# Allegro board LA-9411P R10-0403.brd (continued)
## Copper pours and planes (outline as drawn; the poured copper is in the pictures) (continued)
N78964443 on TOP (solid shape): 69.99,176.45 69.99,174.03 69.73,173.77 67.64,173.77 67.31,174.1 67.31,174.99 67.31,175 67.31,176.42 67.3,176.43 67.3,176.79 67.37,176.86 69.58,176.86
N78967013 on TOP (solid shape): 68.88,172.71 68.88,171.77 68.93,171.72 70.76,171.72 70.84,171.79 71.24,171.79 71.32,171.72 71.32,171.16 71.17,171.01 71.14,171.01 70.91,170.78 68.09,170.78 67.81,171.06 67.81,172.58 68.05,172.82 68.77,172.82
N79030745 on TOP (solid shape): 49.73,173.95 49.73,172.21 49.07,171.55 46.13,171.55 46.02,171.67 46.02,173.28 46.13,173.39 47.51,173.39 48.27,174.15 49.53,174.15
N79031357 on TOP (solid shape): 59.45,179.76 59.9,179.76 60.09,179.58 60.09,178.11 60.02,178.04 59.48,178.04 59.42,178.11 59.42,178.69 59.3,178.8 58.77,178.8 58.19,179.39 57.63,179.39 57.44,179.2 57.44,178.36 57.33,178.24 56.02,178.24 55.88,178.38 55.88,179.95 56.01,180.08 59.13,180.08
N79031404 on TOP (solid shape): 54.86,177.95 54.86,177.51 54.8,177.44 54.35,177.44 53.75,176.85 53.75,176.19 53.59,176.02 52.81,176.02 52.74,176.1 52.74,176.69 52.79,176.75 53.32,176.75 53.77,177.19 53.77,177.76 54.01,178 54.81,178
N79031406 on TOP (solid shape): 53.55,178.55 53.55,177.16 53.4,177.01 52.75,177.01 52.19,176.45 50.53,176.45 50.29,176.69 50.29,177.67 50.53,177.91 52.31,177.91 52.57,178.18 52.57,178.73 52.68,178.83 53.27,178.83
N79031414 on TOP (solid shape): 49.88,180.16 49.88,177.93 49.13,177.18 49.13,176.35 47.99,175.21 47.99,174.07 47.56,173.63 46.5,173.63 46.43,173.71 46.43,176.02 47.75,177.34 47.75,180.44 47.81,180.5 49.54,180.5
N85751870 on TOP (solid shape): 239.63,13.98 239.63,13.22 239.5,13.09 237.22,13.09 237.09,13.22 237.09,13.98 237.22,14.11 239.5,14.11
N91583245 on TOP (solid shape): 346.01,167.88 348.78,167.88 348.8,167.86 348.8,166.38 348.78,166.36 348.03,166.36 347.87,166.51 347.87,166.98 347.61,167.25 346.25,167.25 345.04,168.45 344.38,168.45 344.33,168.5 344.33,168.68 344.39,168.74 345.14,168.74
N111681891 on TOP (solid shape): 189.28,107.51 189.28,105.27 188.9,104.89 187.37,104.89 187.18,105.08 187.18,107.2 187.27,107.29 188.15,107.29 188.4,107.54 189.24,107.54
N116650187 on TOP (solid shape): 114.93,190.13 114.93,188.71 114.78,188.56 113.7,188.56 113.55,188.71 113.55,190.18 113.71,190.35 114.71,190.35
N123100505 on TOP (solid shape): 153.33,6.07 153.33,5.64 153.18,5.49 152.47,5.49 152.16,5.81 152.16,6.36 152.18,6.38 153.02,6.38
N123208235 on TOP (solid shape): 111.55,185.65 111.55,185.11 111.2,184.76 109.08,184.76 108.35,184.04 106.89,184.04 106.65,184.28 106.65,185.71 106.88,185.94 111.26,185.94
N127056523 on TOP (solid shape): 324.65,203.97 324.65,202.76 324.54,202.65 324.54,201.81 324.45,201.72 324.32,201.72 324.24,201.8 324.24,203.14 323.94,203.44 323.94,204.02 323.97,204.05 324.57,204.05
N127056527 on TOP (solid shape): 325.57,203.93 325.57,203.5 325.33,203.26 325.33,201.8 325.27,201.73 325.11,201.73 325.07,201.77 325.07,203.16 324.85,203.39 324.85,203.95 324.92,204.02 325.47,204.02
N127916603 on BOTTOM (solid shape): 343.39,174.13 343.39,172.48 343.26,172.35 342.76,172.35 342.63,172.48 342.63,174.13 342.76,174.26 343.26,174.26
N127916606 on BOTTOM (solid shape): 342.37,174.13 342.37,172.48 342.25,172.35 341.74,172.35 341.61,172.48 341.61,174.13 341.74,174.26 342.25,174.26
N127916609 on BOTTOM (solid shape): 340.47,174.13 340.47,172.48 340.34,172.35 339.83,172.35 339.71,172.48 339.71,174.13 339.83,174.26 340.34,174.26
N127916612 on BOTTOM (solid shape): 341.36,174.13 341.36,172.48 341.23,172.35 340.72,172.35 340.6,172.48 340.6,174.13 340.72,174.26 341.23,174.26

Small or netless copper shapes (teardrops, artwork), in the pictures only: 44 on TOP, 391 on BOTTOM, 1 on GND1, 1 on GND3

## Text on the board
Ref Des/Silkscreen Bottom: LABEL | DDR3L | DIMM A | DIMM B | P
User.Comments: LA-9411P | Lily_tang | 2013-04-03 | 2014-04-03 | VALA0 | 1.0(A00)
Ref Des/Silkscreen Top: 2 | M2.5X5 | H29 | H28 | 1 | 3 | H30 | 4 | H20
BODY_CENTER: trace Width | Width/space | Single 48ohm | Single 46ohm | single 48ohm | single 50ohm | No ref | 6.5mil | 5.1mil | 5mil | 4mil | 5 / 5.5 | 5.5 / 5 | 4.5 / 3.5 | 5 / 4.5 | 4.5 / 4.5 | 5 / 5 | 4 / 4.3 | 4 / 4.5 | 4 / 5 | 4.5 / 7 | 5 / 7 | 4 / 6 | 3.5 / 8 | 3.5 / 5.5 | 3.5 / 6.5 | 7.5 / 5.5 | 10.5 / 5 | HR_1_4mm-10L(4mil 50ohm)_WithOutC_120618 | L1-TOP | L2-GND1 | L3-IN1 | L4-GND2 | L5-IN2 | L6-IN3 | L7-VCC | L8-IN4 | L9-GND3 | L10-BOT | LAYER | NAME | STACKUP: 10 LAYER | 39(40) | ohm | 45 ohm | THICKNESS=1.4mm | 50 ohm | 80 ohm | 85 ohm | 88 ohm | 90 ohm | 100 ohm
COMPVAL_TYPE_TOP: FIGURE | SIZE | 8.0 | 10.0 | 22.0 | 24.0 | 28.0 | 31.0 | 35.0 | 39.0 | 91.0 | 110.0 | 138.0 | 150.0 | 189.0 | 244.0 | 26.0 | 37.0 | 40.0 | 43.0 | 47.0 | 63.0 | 45.0x37.0 | 49.0x33.0 | 55.0x24.0 | 63.0x35.0 | 69.0x20.0 | 71.0x31.0 | 75.0x37.0 | 91.0x28.0 | 94.0x39.0 | 98.0x39.0 | 102.0x31.0 | 112.0x39.0 | 118.0x33.0 | 315.0x98.0 | 67.0x43.0 | DRILL CHART: TOP to BOTTOM | ALL UNITS ARE IN MILS | PLATED | NON-PLATED | QTY | 8168 | 1717 | 19 | 31 | 36 | 6 | 13 | 4 | 14 | 7 | 2 | 1 | 5
